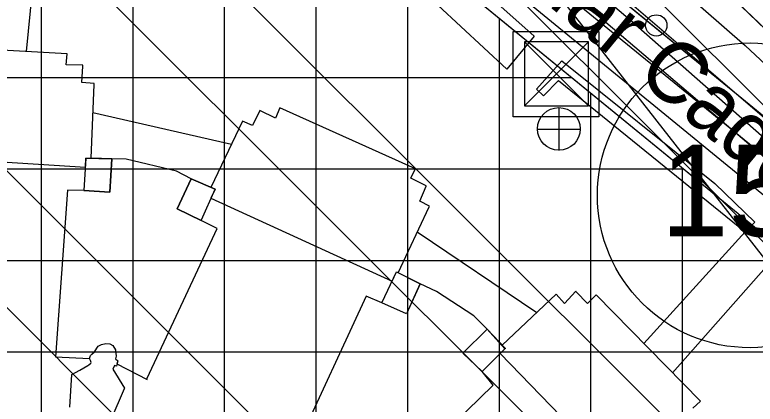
# Model space of a CAD drawing. Extents: x 417995 to 421451, y 4454518 to 4458015.
# Drawn here: x 420576.3 to 420697.6, y 4456517.4 to 4456581.3 of the extents above; entities that cross this region are included whole.
import ezdxf

# ---------------------------------------------------------------- set-up
doc = ezdxf.new("R2010")
doc.units = 0
for name, color, linetype in [('ADAKENARI', 7, 'Continuous'), ('B_Imalat', 7, 'Continuous'), ('B_Teras', 7, 'Continuous'), ('KALDIRIM_FAT', 7, 'Continuous'), ('KD_DAIRE', 7, 'Continuous'), ('KD_YGEN', 7, 'Continuous'), ('PL_AYA_PARK_DINLENME', 7, 'Continuous'), ('PL_TİCARET', 7, 'Continuous'), ('S_Bekci_Kulubesi', 7, 'Continuous'), ('S_Cad_Sok_Lambasi', 7, 'Continuous'), ('S_Rogar_Kapagi', 7, 'Continuous'), ('Sev_Sevalti', 7, 'Continuous'), ('Sinir_Ist_Duvari', 7, 'Continuous'), ('Sinir_Tel_bir_taraf', 7, 'Continuous'), ('SN_TASKIN', 7, 'Continuous'), ('SN_TR_SIVILASMA', 7, 'Continuous'), ('TRFAT_PARKALANI', 7, 'Continuous'), ('TRFAT_TİCARET', 7, 'Continuous'), ('Y_Cadde_Yol', 7, 'Continuous'), ('Yol_Kaldirim_kenari_bordurtasi', 7, 'Continuous'), ('Yol_Sose', 7, 'Continuous')]:
    doc.layers.add(name, color=color, linetype=linetype)

msp = doc.modelspace()

# ---------------------------------------------------------------- linework, layer by layer
at = {"layer": 'ADAKENARI'}
for p, q in [((420578.41, 4456663.41), (420752.58, 4456520.73)), ((420648.52, 4456627.66), (420768.79, 4456512.12)), ((420605.44, 4456621.88), (420740.82, 4456510.98))]:
    msp.add_line(p, q, dxfattribs=at)
msp.add_arc((420191.41, 4456074.8), 823.13, 35.35416, 63.79989, dxfattribs=at)
at = {"layer": 'B_Imalat'}
msp.add_lwpolyline([(420687.4, 4456516.72), (420688.63, 4456517.88), (420671.55, 4456535.31), (420670.13, 4456533.91), (420670.13, 4456533.91), (420668.27, 4456535.83), (420668.24, 4456535.94), (420666.35, 4456533.92), (420665.01, 4456535.44), (420656.18, 4456527.06), (420653.68, 4456529.69), (420651.49, 4456531.87), (420645.37, 4456535.88), (420642.7, 4456537.16), (420639.1, 4456538.95), (420644.19, 4456549.79), (420644.26, 4456549.9), (420642.65, 4456550.69), (420642.65, 4456550.69), (420643.68, 4456553.15), (420643.73, 4456553.22), (420641.21, 4456554.49), (420641.9, 4456555.94), (420641.97, 4456556.01), (420619.74, 4456565.99), (420619.02, 4456564.31), (420616.45, 4456565.57), (420616.45, 4456565.57), (420615.27, 4456563.11), (420613.63, 4456563.84), (420613.63, 4456563.84), (420608.42, 4456552.95), (420605.2, 4456554.35), (420602.81, 4456555.61), (420594.54, 4456557.61), (420594.54, 4456557.61), (420592.22, 4456557.64), (420588.81, 4456557.73), (420589.3, 4456569.85), (420589.33, 4456569.99), (420587.28, 4456570.14), (420587.28, 4456570.14), (420587.47, 4456572.83), (420587.48, 4456572.99), (420584.74, 4456573.07), (420584.74, 4456573.07), (420584.89, 4456574.87), (420584.89, 4456574.87), (420560.51, 4456576.25)], dxfattribs=at)
at = {"layer": 'B_Teras'}
for points in [[(420555.28, 4456558.36), (420587.89, 4456556.27), (420587.98, 4456557.75), (420592.22, 4456557.64), (420591.91, 4456552.16), (420587.65, 4456552.43), (420584.95, 4456552.51), (420582.98, 4456525.18), (420588.56, 4456524.91), (420588.72, 4456525.39), (420588.92, 4456525.61), (420589.36, 4456526), (420589.99, 4456526.92), (420590.54, 4456527.19), (420591.23, 4456527.36), (420591.89, 4456527.31), (420592.38, 4456527), (420592.79, 4456526.3), (420592.93, 4456525.29), (420592.82, 4456524.84), (420593.19, 4456524.51), (420593.06, 4456524.01), (420597.99, 4456521.43), (420598, 4456521.65), (420609.46, 4456546.2), (420606.85, 4456547.55), (420602.93, 4456549.42), (420605.2, 4456554.35), (420609.13, 4456552.64), (420608.46, 4456551.17), (420638.14, 4456537.57), (420638.85, 4456539.08), (420642.7, 4456537.16), (420640.47, 4456532.22), (420636.45, 4456534.02), (420633.86, 4456535.11), (420622.48, 4456510.43)], [(420637.57, 4456503.82), (420654.67, 4456520.54), (420652.86, 4456522.76), (420649.69, 4456525.78), (420653.68, 4456529.69), (420656.58, 4456526.45), (420655.84, 4456525.71), (420677.4, 4456503.4)], [(420585.32, 4456516.92), (420585.67, 4456522.26), (420587, 4456522.96), (420588.29, 4456523.74), (420588.44, 4456523.83), (420588.75, 4456524.13), (420588.85, 4456524.24), (420588.72, 4456524.58), (420588.56, 4456524.91), (420588.72, 4456525.39), (420588.92, 4456525.61), (420589.36, 4456526), (420589.99, 4456526.92), (420590.54, 4456527.19), (420591.23, 4456527.36), (420591.89, 4456527.31), (420592.38, 4456527), (420592.79, 4456526.3), (420592.93, 4456525.29), (420592.93, 4456525.27), (420592.82, 4456524.84), (420593.19, 4456524.51), (420592.97, 4456523.66), (420592.67, 4456523.74), (420592.38, 4456523.16), (420594.28, 4456520), (420594.25, 4456519.92), (420592.04, 4456514.84)]]:
    msp.add_lwpolyline(points, dxfattribs=at)
for points in [[(420587.98, 4456557.75), (420587.65, 4456552.43), (420587.65, 4456552.43), (420591.91, 4456552.16), (420591.91, 4456552.16), (420592.22, 4456557.64)], [(420605.2, 4456554.35), (420602.93, 4456549.42), (420606.85, 4456547.55), (420606.88, 4456547.66), (420609.13, 4456552.64)], [(420638.85, 4456539.08), (420638.85, 4456539.08), (420642.7, 4456537.16), (420642.67, 4456537.11), (420640.47, 4456532.22), (420636.45, 4456534.02)], [(420653.68, 4456529.69), (420653.68, 4456529.69), (420656.68, 4456526.53), (420656.58, 4456526.45), (420652.86, 4456522.76), (420652.86, 4456522.76), (420649.69, 4456525.78)]]:
    msp.add_lwpolyline(points, close=True, dxfattribs=at)
at = {"layer": 'KALDIRIM_FAT'}
for p, q in [((420561.09, 4456671.14), (420745.28, 4456520.25)), ((420609.07, 4456625.37), (420742.12, 4456516.38))]:
    msp.add_line(p, q, dxfattribs=at)
at = {"layer": 'KD_DAIRE'}
msp.add_circle((420696.76, 4456551.65), 25, dxfattribs=at)
at = {"layer": 'PL_AYA_PARK_DINLENME'}
msp.add_lwpolyline([(420748.16, 4456516.17), (420745.66, 4456518.22), (420541.58, 4456692.09), (420537.09, 4456695.76), (420532.45, 4456699.23), (420527.67, 4456702.5), (420522.75, 4456705.56), (420517.7, 4456708.42), (420512.54, 4456711.05), (420507.27, 4456713.47), (420501.91, 4456715.66), (420360.26, 4456770.01), (420355.91, 4456776.8), (420359.27, 4456828.3)], dxfattribs=at)
msp.add_lwpolyline([(420756.36, 4456492.63), (420757.5, 4456509.37), (420757.51, 4456510.98), (420757.34, 4456512.57), (420756.97, 4456514.14), (420756.42, 4456515.65), (420755.7, 4456517.08), (420754.81, 4456518.42), (420753.76, 4456519.64), (420752.58, 4456520.73), (420578.41, 4456663.41), (420580.89, 4456666.43), (420648.52, 4456627.66), (420768.79, 4456512.12), (420781.13, 4456491.97)], close=True, dxfattribs=at)
at = {"layer": 'PL_TİCARET'}
msp.add_lwpolyline([(420385.69, 4456393.42), (420394.63, 4456520.03), (420397.17, 4456524), (420597.45, 4456622.21), (420600.7, 4456622.93), (420603.05, 4456622.66), (420605.44, 4456621.88), (420740.82, 4456510.98)], dxfattribs=at)
at = {"layer": 'S_Bekci_Kulubesi'}
for p, q in [((420659.81, 4456566.31), (420670.31, 4456576.81)), ((420659.81, 4456576.81), (420670.31, 4456566.31)), ((420670.31, 4456576.81), (420659.81, 4456576.81)), ((420659.81, 4456576.81), (420659.81, 4456566.31)), ((420670.31, 4456566.31), (420670.31, 4456576.81)), ((420659.81, 4456566.31), (420670.31, 4456566.31))]:
    msp.add_line(p, q, dxfattribs=at)
msp.add_lwpolyline([(420657.96, 4456578.52), (420671.96, 4456578.52), (420671.96, 4456564.52), (420657.96, 4456564.52)], close=True, dxfattribs=at)
at = {"layer": 'S_Cad_Sok_Lambasi'}
msp.add_circle((420681.39, 4456579.52), 1.75, dxfattribs=at)
at = {"layer": 'S_Rogar_Kapagi'}
for p, q in [((420665.5, 4456559.02), (420665.5, 4456566.02)), ((420661.93, 4456562.49), (420668.93, 4456562.49))]:
    msp.add_line(p, q, dxfattribs=at)
msp.add_circle((420665.45, 4456562.55), 3.5, dxfattribs=at)
at = {"layer": 'Sev_Sevalti'}
msp.add_lwpolyline([(420541.24, 4456707.54), (420549.93, 4456692.47), (420555.55, 4456684.39), (420573.51, 4456672.67), (420586.73, 4456663.16), (420599.75, 4456654.2), (420614.42, 4456644.85), (420618.88, 4456640.9), (420620.67, 4456643.12), (420633.4, 4456631.82), (420629.71, 4456627.87), (420643.09, 4456619.42), (420656.67, 4456608.9), (420665.25, 4456601.78), (420679.18, 4456590.93), (420695.96, 4456576.25), (420710.17, 4456562.95), (420723.4, 4456548.29), (420734.56, 4456538.68), (420743.79, 4456529.3), (420754.35, 4456517.11)], dxfattribs=at)
at = {"layer": 'Sinir_Ist_Duvari'}
for points in [[(420589.11, 4456565.26), (420611.82, 4456560.05)], [(420642.25, 4456545.67), (420661.81, 4456532.41)]]:
    msp.add_lwpolyline(points, dxfattribs=at)
at = {"layer": 'Sinir_Tel_bir_taraf'}
for points in [[(420582.13, 4456615.3), (420578.2, 4456575.25)], [(420679.37, 4456527.33), (420695.98, 4456545.68)], [(420701.46, 4456542.3), (420684.07, 4456522.53)]]:
    msp.add_lwpolyline(points, dxfattribs=at)
at = {"layer": 'SN_TASKIN'}
msp.add_lwpolyline([(421279.09, 4456215.61), (421195.31, 4456240.09), (421032.23, 4456272.97), (420928.59, 4456320.69), (420834.21, 4456393.35), (420746.64, 4456480.52), (420663.92, 4456586.47), (420574.11, 4456669.5), (420422.96, 4456744.08), (420282.11, 4456812), (420160.8, 4456835.05), (420091.41, 4456837.4), (419960.89, 4456961.81), (419854.4, 4457049.62), (419750.61, 4457217.33), (419705.67, 4457319.89), (419669.27, 4457550.58), (419656.39, 4457729.95), (419636.42, 4457793.06)], dxfattribs=at)
at = {"layer": 'SN_TR_SIVILASMA'}
for p, q in [((421276.73, 4455988.66), (419957.49, 4457307.89)), ((421276.49, 4455966.44), (419971.97, 4457270.96)), ((421276.03, 4455922), (420004.05, 4457193.98)), ((421275.8, 4455899.78), (420015.35, 4457160.22)), ((421275.33, 4455855.34), (420037.81, 4457092.87)), ((421275.1, 4455833.12), (420049.03, 4457059.2))]:
    msp.add_line(p, q, dxfattribs=at)
at = {"layer": 'TRFAT_PARKALANI'}
msp.add_line((420679.51, 4456580.88), (420679.51, 4456580.88), dxfattribs=at)
at = {"layer": 'TRFAT_TİCARET'}
for p, q in [((420595.69, 4456336.34), (420595.69, 4456621.35)), ((420610.69, 4456335.38), (420610.69, 4456617.58)), ((420580.69, 4456337.31), (420580.69, 4456613.99)), ((420625.69, 4456333.22), (420625.69, 4456605.29)), ((420640.69, 4456031.44), (420640.69, 4456593)), ((420655.69, 4456033.98), (420655.69, 4456580.72)), ((420493, 4456570.99), (420667.56, 4456570.99)), ((420670.69, 4456344.64), (420670.69, 4456568.43)), ((420462.41, 4456555.99), (420685.87, 4456555.99)), ((420685.69, 4456344.64), (420685.69, 4456556.14)), ((420431.82, 4456540.99), (420704.19, 4456540.99)), ((420401.23, 4456525.99), (420722.5, 4456525.99))]:
    msp.add_line(p, q, dxfattribs=at)
at = {"layer": 'Yol_Kaldirim_kenari_bordurtasi'}
msp.add_lwpolyline([(420755, 4456502.51), (420755.27, 4456514.1), (420739.38, 4456531.58), (420715.02, 4456550.81), (420697.98, 4456565.3), (420676.94, 4456583.32), (420650.42, 4456604.78), (420632.93, 4456619.66), (420625.5, 4456625.05), (420626.26, 4456626.04), (420610.45, 4456639.12), (420581.78, 4456660.91), (420561.96, 4456675.41)], dxfattribs=at)
at = {"layer": 'Yol_Sose'}
for points in [[(420511.22, 4456721.19), (420526.77, 4456711.23), (420538.38, 4456702.38), (420552.5, 4456686.15), (420564.13, 4456672.95), (420595.08, 4456648.26), (420618.65, 4456629.62), (420652.2, 4456601.23), (420663.46, 4456592.08), (420677.14, 4456580.46), (420699.97, 4456560.25), (420723.19, 4456542.88), (420738.51, 4456530.28), (420745.35, 4456523.33), (420753.67, 4456513.82), (420754.01, 4456506.59)], [(420582.13, 4456615.3), (420595.01, 4456623.03), (420597.04, 4456623.99), (420598.67, 4456624.2), (420600.09, 4456624.23), (420601.72, 4456624.17), (420605.86, 4456623.19), (420611.32, 4456620.48), (420637.67, 4456598.95), (420661.39, 4456577.75), (420656.94, 4456572.33)], [(420582.13, 4456615.3), (420582.9, 4456614.12), (420595.3, 4456621.5), (420597.9, 4456621.94), (420599.91, 4456621.95), (420602.08, 4456621.86), (420604.78, 4456621.29), (420606.65, 4456620.6), (420640.59, 4456591.38), (420647.59, 4456585.59), (420645.6, 4456582.86), (420656.94, 4456572.33)], [(420661.76, 4456569.05), (420665.93, 4456573.7), (420691.01, 4456553.61), (420697.54, 4456547.26)], [(420661.76, 4456569.05), (420662.93, 4456568), (420665.38, 4456570.5), (420695.98, 4456545.68), (420697.54, 4456547.26)], [(420661.76, 4456569.05), (420662.93, 4456568), (420665.38, 4456570.5), (420695.98, 4456545.68), (420697.54, 4456547.26)]]:
    msp.add_lwpolyline(points, dxfattribs=at)

# ---------------------------------------------------------------- texts
at = {"layer": 'KD_YGEN'}
msp.add_text('15', height=15, dxfattribs=at).set_placement((420682.1, 4456544.95))
at = {"layer": 'Y_Cadde_Yol'}
msp.add_text('Fuar Caddesi', height=10, rotation=320.4511, dxfattribs=at).set_placement((420653.73, 4456591))

doc.saveas('drawing.dxf')
